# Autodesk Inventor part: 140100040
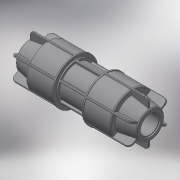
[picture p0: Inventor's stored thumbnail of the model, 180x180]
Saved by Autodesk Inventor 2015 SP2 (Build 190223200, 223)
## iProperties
Created: 2018-02
Part Number: 140100040
Material: Generic
Description: PLASSON L.14 COUPLER (SILVER) 40
Document SubType Name: Modeling
Designer: KIM
Mass: 258.55 g
Surface Area: 537.794 cm^2
Volume: 258.55 cm^3
Density: 1 g/cm^3
Appearance: Default
Author: KIM
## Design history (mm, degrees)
derived "140100.ipt"
feature "Solid1::140100.ipt"
tag "TaggingFeature1"
body "Solid1"
other parameters: "d30" = 1, "d36" = 1.27, "d65" = 70.81, "d77" = 36.8, "d93" = 56, "d95" = 19.05, "d96" = 1.27, "d97" = 44, "d100" = 54.75, "d102" = 48.26, "d103" = 1.27, "d107" = 62.65, "d113" = 73, "d114" = 4, "d115" = 2, "d117" = 0, "d126" = 7.3, "d127" = 0.73, "d129" = 360 deg, "d131" = 1.27, "d132" = 73, "d138" = 100 deg, "d139" = 62.05, "d141" = 127, "d143" = 62, "d144" = 0, "d146" = 62, "d147" = 0, "d149" = 3.65, "d150" = 1.825, "d152" = 0, "d153" = 0.73, "d155" = 360 deg, "E_" = 73, "l_" = 62, "H_" = 127
